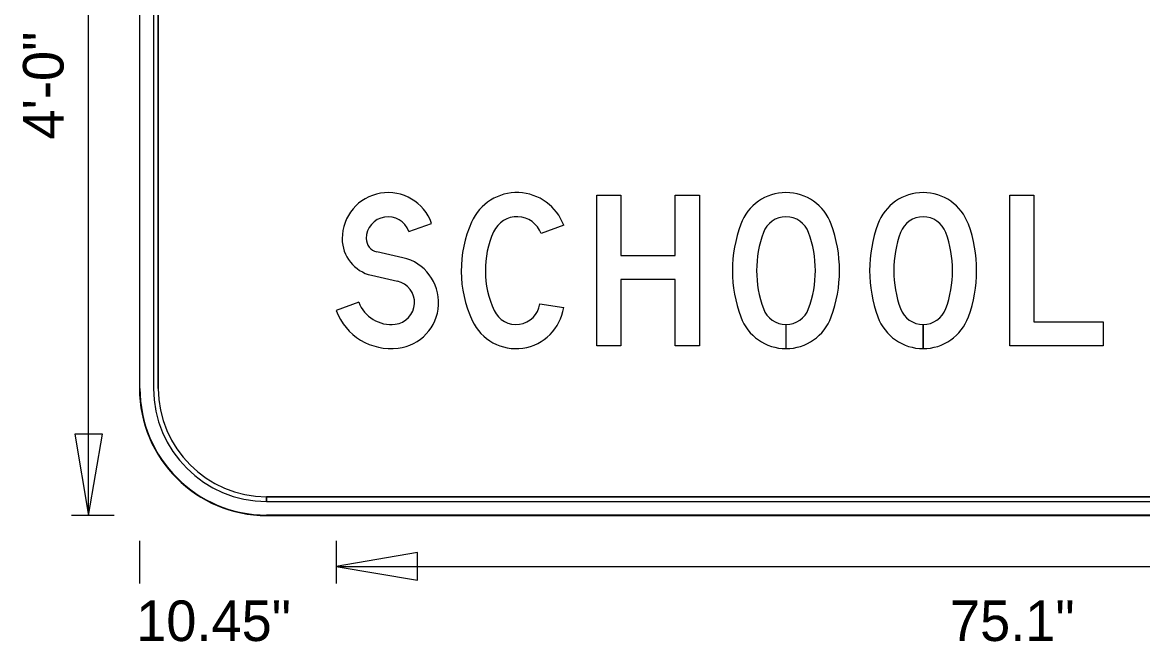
# Model space of a CAD drawing. Extents: x 0 to 770, y 0 to 495.
# Drawn here: x 582.9 to 679.6, y 379.4 to 432.8 of the extents above; entities that cross this region are included whole.
import ezdxf

# ---------------------------------------------------------------- set-up
doc = ezdxf.new("R2010")
doc.units = 0
for name, color, linetype in [('Dimension', 7, 'Continuous'), ('GSBWFill', 7, 'Continuous'), ('GSColorFill', 7, 'Continuous'), ('GSDims', 7, 'Continuous'), ('GSOutline', 7, 'Continuous'), ('TextStructures', 7, 'Continuous')]:
    doc.layers.add(name, color=color, linetype=linetype)

msp = doc.modelspace()

# ---------------------------------------------------------------- linework, layer by layer
at = {"layer": 'Dimension'}
for points in [[(588.596, 390.237), (589.785, 397.254), (587.408, 397.254)], [(609.979, 385.844), (616.995, 384.655), (616.995, 387.032)]]:
    msp.add_lwpolyline(points, close=True, dxfattribs=at)
at = {"layer": 'GSBWFill'}
for p, q in [((592.99, 457.362), (592.99, 401.221)), ((594.21, 457.362), (594.21, 401.221)), ((594.617, 401.221), (594.617, 457.362)), ((616.253, 414.777), (618.221, 415.46)), ((629.636, 415.304), (627.679, 414.59)), ((615.741, 412.505), (613.494, 413.016)), ((613.032, 410.985), (615.279, 410.474)), ((611.928, 408.676), (609.979, 407.942)), ((627.576, 408.513), (629.636, 408.205)), ((648.838, 406.738), (648.838, 404.655)), ((648.839, 404.655), (648.839, 406.738)), ((660.685, 404.655), (660.685, 406.738)), ((660.685, 406.738), (660.685, 404.655)), ((603.974, 391.458), (603.974, 391.864)), ((738.224, 391.864), (603.978, 391.864)), ((603.978, 391.864), (603.978, 391.458)), ((603.978, 391.458), (738.224, 391.458)), ((603.974, 390.237), (738.224, 390.237))]:
    msp.add_line(p, q, dxfattribs=at)
for points in [[(632.5, 417.901), (634.583, 417.901), (634.583, 412.694), (639.27, 412.694), (639.27, 417.901), (641.353, 417.901), (641.353, 404.883), (639.27, 404.883), (639.27, 410.611), (634.583, 410.611), (634.583, 404.883), (632.5, 404.883)], [(670.253, 406.966), (676.241, 406.966), (676.241, 404.883), (668.17, 404.883), (668.17, 417.901), (670.253, 417.901)]]:
    msp.add_lwpolyline(points, close=True, dxfattribs=at)
for centre, radius, start, end in [((614.47, 414.158), 3.971, 19.13948, 180), ((614.47, 414.158), 1.888, 19.13948, 180), ((613.754, 414.158), 3.255, 180, 257.19149), ((613.754, 414.158), 1.172, 180, 257.19149), ((614.861, 408.633), 3.971, 276.78539, 77.19149), ((614.861, 408.633), 1.888, 276.78539, 77.19149), ((614.73, 409.732), 2.994, 200.64423, 276.78539), ((614.73, 409.732), 5.077, 200.64423, 276.78539), ((603.974, 401.221), 10.984, 180, 270), ((603.974, 401.221), 9.764, 180, 270), ((603.974, 401.221), 9.357, 180, 270)]:
    msp.add_arc(centre, radius, start, end, dxfattribs=at)
for centre, major_axis, start_param, end_param in [((625.6, 413.833), (0, 4.296), 5.061866, 7.434148), ((648.838, 413.963), (0, 4.166), 5.063177, 7.503193), ((660.685, 413.963), (0, 4.166), 5.063177, 7.503193), ((631.068, 411.392), (0, 10.284), 1.150963, 2.004476), ((625.6, 413.833), (0, 2.213), 5.061866, 7.434148), ((655.864, 411.392), (0, 11.648), 1.220008, 1.921585), ((648.838, 413.963), (0, 2.083), 5.063177, 7.503193), ((641.812, 411.392), (0, 11.648), 4.361601, 5.063177), ((667.711, 411.392), (0, 11.648), 1.220008, 1.921585), ((660.685, 413.963), (0, 2.083), 5.063177, 7.503193), ((653.658, 411.392), (0, 11.648), 4.361601, 5.063177), ((631.068, 411.392), (0, 8.201), 1.150963, 2.004476), ((655.864, 411.392), (0, 9.565), 1.220008, 1.921585), ((641.812, 411.392), (0, 9.565), 4.361601, 5.063177), ((667.711, 411.392), (0, 9.565), 1.220008, 1.921585), ((653.658, 411.392), (0, 9.565), 4.361601, 5.063177), ((625.516, 408.821), (0, 2.083), 2.004476, 4.564141), ((625.516, 408.821), (0, 4.166), 2.004476, 4.564141), ((648.838, 408.821), (0, 4.166), 1.921585, 3.141593), ((648.838, 408.821), (0, 2.083), 1.921585, 3.141593), ((648.838, 408.821), (0, 2.083), 3.141905, 4.361601), ((648.838, 408.821), (0, 4.166), 3.141749, 4.361601), ((660.685, 408.821), (0, 4.166), 1.921585, 3.141593), ((660.685, 408.821), (0, 2.083), 1.921585, 3.141593), ((660.685, 408.821), (0, 2.083), 3.141905, 4.361601), ((660.685, 408.821), (0, 4.166), 3.141749, 4.361601)]:
    msp.add_ellipse(centre, major_axis=major_axis, ratio=0.999993, start_param=start_param, end_param=end_param, dxfattribs=at)
at = {"layer": 'GSColorFill'}
for p, q in [((592.99, 457.362), (592.99, 401.221)), ((592.99, 457.362), (592.99, 401.221)), ((593.031, 401.221), (593.031, 457.362)), ((594.21, 457.362), (594.21, 401.221)), ((594.617, 401.221), (594.617, 457.362)), ((616.253, 414.777), (618.221, 415.46)), ((629.636, 415.304), (627.679, 414.59)), ((615.741, 412.505), (613.494, 413.016)), ((613.032, 410.985), (615.279, 410.474)), ((611.928, 408.676), (609.979, 407.942)), ((627.576, 408.513), (629.636, 408.205)), ((648.838, 406.738), (648.838, 404.655)), ((648.839, 404.655), (648.839, 406.738)), ((660.685, 404.655), (660.685, 406.738)), ((660.685, 406.738), (660.685, 404.655)), ((603.974, 391.458), (603.974, 391.864)), ((738.224, 391.864), (603.978, 391.864)), ((603.978, 391.864), (603.978, 391.458)), ((603.978, 391.458), (738.224, 391.458)), ((603.974, 390.237), (603.974, 390.278)), ((603.974, 390.237), (738.224, 390.237)), ((738.224, 390.278), (603.975, 390.278)), ((603.975, 390.278), (603.975, 390.237)), ((603.975, 390.237), (738.224, 390.237))]:
    msp.add_line(p, q, dxfattribs=at)
for points in [[(632.5, 417.901), (634.583, 417.901), (634.583, 412.694), (639.27, 412.694), (639.27, 417.901), (641.353, 417.901), (641.353, 404.883), (639.27, 404.883), (639.27, 410.611), (634.583, 410.611), (634.583, 404.883), (632.5, 404.883)], [(670.253, 406.966), (676.241, 406.966), (676.241, 404.883), (668.17, 404.883), (668.17, 417.901), (670.253, 417.901)]]:
    msp.add_lwpolyline(points, close=True, dxfattribs=at)
for centre, radius, start, end in [((614.47, 414.158), 3.971, 19.13948, 180), ((614.47, 414.158), 1.888, 19.13948, 180), ((613.754, 414.158), 3.255, 180, 257.19149), ((613.754, 414.158), 1.172, 180, 257.19149), ((614.861, 408.633), 3.971, 276.78539, 77.19149), ((614.861, 408.633), 1.888, 276.78539, 77.19149), ((614.73, 409.732), 2.994, 200.64423, 276.78539), ((614.73, 409.732), 5.077, 200.64423, 276.78539), ((603.974, 401.221), 10.984, 180, 270), ((603.974, 401.221), 10.984, 180, 270), ((603.974, 401.221), 10.943, 180, 270), ((603.974, 401.221), 9.764, 180, 270), ((603.974, 401.221), 9.357, 180, 270)]:
    msp.add_arc(centre, radius, start, end, dxfattribs=at)
for centre, major_axis, start_param, end_param in [((625.6, 413.833), (0, 4.296), 5.061866, 7.434148), ((648.838, 413.963), (0, 4.166), 5.063177, 7.503193), ((660.685, 413.963), (0, 4.166), 5.063177, 7.503193), ((631.068, 411.392), (0, 10.284), 1.150963, 2.004476), ((625.6, 413.833), (0, 2.213), 5.061866, 7.434148), ((655.864, 411.392), (0, 11.648), 1.220008, 1.921585), ((648.838, 413.963), (0, 2.083), 5.063177, 7.503193), ((641.812, 411.392), (0, 11.648), 4.361601, 5.063177), ((667.711, 411.392), (0, 11.648), 1.220008, 1.921585), ((660.685, 413.963), (0, 2.083), 5.063177, 7.503193), ((653.658, 411.392), (0, 11.648), 4.361601, 5.063177), ((631.068, 411.392), (0, 8.201), 1.150963, 2.004476), ((655.864, 411.392), (0, 9.565), 1.220008, 1.921585), ((641.812, 411.392), (0, 9.565), 4.361601, 5.063177), ((667.711, 411.392), (0, 9.565), 1.220008, 1.921585), ((653.658, 411.392), (0, 9.565), 4.361601, 5.063177), ((625.516, 408.821), (0, 2.083), 2.004476, 4.564141), ((625.516, 408.821), (0, 4.166), 2.004476, 4.564141), ((648.838, 408.821), (0, 4.166), 1.921585, 3.141593), ((648.838, 408.821), (0, 2.083), 1.921585, 3.141593), ((648.838, 408.821), (0, 2.083), 3.141905, 4.361601), ((648.838, 408.821), (0, 4.166), 3.141749, 4.361601), ((660.685, 408.821), (0, 4.166), 1.921585, 3.141593), ((660.685, 408.821), (0, 2.083), 1.921585, 3.141593), ((660.685, 408.821), (0, 2.083), 3.141905, 4.361601), ((660.685, 408.821), (0, 4.166), 3.141749, 4.361601)]:
    msp.add_ellipse(centre, major_axis=major_axis, ratio=0.999993, start_param=start_param, end_param=end_param, dxfattribs=at)
at = {"layer": 'GSDims'}
for p, q in [((588.596, 390.237), (588.596, 468.346)), ((590.793, 390.237), (587.132, 390.237)), ((592.99, 388.04), (592.99, 384.379)), ((609.979, 388.04), (609.979, 384.379)), ((609.979, 388.04), (609.979, 384.379)), ((609.979, 385.844), (732.22, 385.844))]:
    msp.add_line(p, q, dxfattribs=at)
at = {"layer": 'GSOutline'}
for p, q in [((592.99, 457.362), (592.99, 401.221)), ((594.21, 457.362), (594.21, 401.221)), ((594.617, 457.362), (594.617, 401.221)), ((616.253, 414.777), (618.221, 415.46)), ((629.636, 415.304), (627.679, 414.59)), ((615.741, 412.505), (613.494, 413.016)), ((613.032, 410.985), (615.279, 410.474)), ((611.928, 408.676), (609.979, 407.942)), ((627.576, 408.513), (629.636, 408.205)), ((603.974, 391.864), (738.224, 391.864)), ((603.974, 391.458), (738.224, 391.458)), ((603.974, 390.237), (738.224, 390.237))]:
    msp.add_line(p, q, dxfattribs=at)
for points in [[(632.5, 417.901), (634.583, 417.901), (634.583, 412.694), (639.27, 412.694), (639.27, 417.901), (641.353, 417.901), (641.353, 404.883), (639.27, 404.883), (639.27, 410.611), (634.583, 410.611), (634.583, 404.883), (632.5, 404.883)], [(670.253, 406.966), (676.241, 406.966), (676.241, 404.883), (668.17, 404.883), (668.17, 417.901), (670.253, 417.901)]]:
    msp.add_lwpolyline(points, close=True, dxfattribs=at)
for centre, radius, start, end in [((614.47, 414.158), 3.971, 19.13948, 180), ((614.47, 414.158), 1.888, 19.13948, 180), ((613.754, 414.158), 3.255, 180, 257.19149), ((613.754, 414.158), 1.172, 180, 257.19149), ((614.861, 408.633), 3.971, 276.78539, 77.19149), ((614.861, 408.633), 1.888, 276.78539, 77.19149), ((614.73, 409.732), 2.994, 200.64423, 276.78539), ((614.73, 409.732), 5.077, 200.64423, 276.78539), ((603.974, 401.221), 10.984, 180, 270), ((603.974, 401.221), 9.764, 180, 270), ((603.974, 401.221), 9.357, 180, 270)]:
    msp.add_arc(centre, radius, start, end, dxfattribs=at)
for centre, major_axis, start_param, end_param in [((625.6, 413.833), (0, 4.296), 5.061866, 7.434148), ((648.838, 413.963), (0, 4.166), 5.063177, 7.503193), ((660.685, 413.963), (0, 4.166), 5.063177, 7.503193), ((631.068, 411.392), (0, 10.284), 1.150963, 2.004476), ((625.6, 413.833), (0, 2.213), 5.061866, 7.434148), ((655.864, 411.392), (0, 11.648), 1.220008, 1.921585), ((648.838, 413.963), (0, 2.083), 5.063177, 7.503193), ((641.812, 411.392), (0, 11.648), 4.361601, 5.063177), ((667.711, 411.392), (0, 11.648), 1.220008, 1.921585), ((660.685, 413.963), (0, 2.083), 5.063177, 7.503193), ((653.658, 411.392), (0, 11.648), 4.361601, 5.063177), ((631.068, 411.392), (0, 8.201), 1.150963, 2.004476), ((655.864, 411.392), (0, 9.565), 1.220008, 1.921585), ((641.812, 411.392), (0, 9.565), 4.361601, 5.063177), ((667.711, 411.392), (0, 9.565), 1.220008, 1.921585), ((653.658, 411.392), (0, 9.565), 4.361601, 5.063177), ((625.516, 408.821), (0, 2.083), 2.004476, 4.564141), ((625.516, 408.821), (0, 4.166), 2.004476, 4.564141), ((648.838, 408.821), (0, 4.166), 1.921585, 4.361601), ((648.838, 408.821), (0, 2.083), 1.921585, 4.361601), ((660.685, 408.821), (0, 4.166), 1.921585, 4.361601), ((660.685, 408.821), (0, 2.083), 1.921585, 4.361601)]:
    msp.add_ellipse(centre, major_axis=major_axis, ratio=0.999993, start_param=start_param, end_param=end_param, dxfattribs=at)

# ---------------------------------------------------------------- texts
at = {"layer": 'TextStructures'}
msp.add_text('4\'-0"', height=3.5, rotation=90, dxfattribs=at).set_placement((586.431, 422.709))
for s, p in [('10.45"', (592.705, 379.401)), ('75.1"', (663.002, 379.401))]:
    msp.add_text(s, height=3.5, dxfattribs=at).set_placement(p)

doc.saveas('drawing.dxf')
